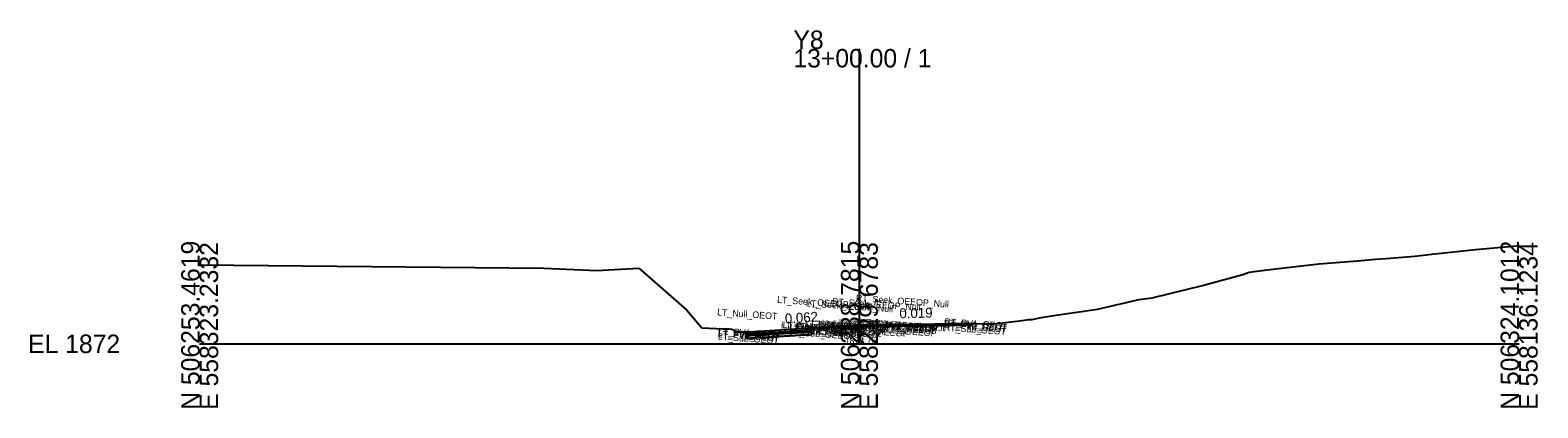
# Model space of a CAD drawing. Extents: x -26 to 203, y -10 to 8070.
# Drawn here: x -25.7 to 202.8, y 2990.3 to 3047.5 of the extents above; entities that cross this region are included whole.
import ezdxf

# ---------------------------------------------------------------- set-up
doc = ezdxf.new("R2010")
doc.units = 0
for name, color, linetype in [('Default', 7, 'Continuous'), ('Exist Cross Section Cell', 7, 'Continuous'), ('Exist XS Center Line Elevation Label', 7, 'Continuous'), ('Exist XS Ground Line', 7, 'Continuous'), ('Prop CMT Pvmt Course 1', 7, 'Continuous'), ('Prop CMT Pvmt Course 2', 7, 'Continuous'), ('Prop CMT Pvmt Course 3', 7, 'Continuous'), ('Prop CMT Pvmt Surface', 7, 'Continuous'), ('Prop CMT Subgrade Earthwork', 7, 'Continuous'), ('Prop XS Earthwork Shape', 7, 'Continuous'), ('Prop XS SE Text', 7, 'Continuous'), ('Typical Text Grade Point CELL', 7, 'Continuous')]:
    doc.layers.add(name, color=color, linetype=linetype)

msp = doc.modelspace()

# ---------------------------------------------------------------- linework, layer by layer
at = {"layer": 'Exist Cross Section Cell'}
for p, q in [((100, 3000), (100, 3044.65)), ((0, 3000), (100, 3000)), ((100, 3000), (200, 3000))]:
    msp.add_line(p, q, dxfattribs=at)
at = {"layer": 'Exist XS Ground Line'}
for p, q in [((193.38, 3014.3), (199.06, 3014.81)), ((199.06, 3014.81), (200, 3014.88)), ((161.8, 3011.18), (169.66, 3012.1)), ((169.66, 3012.1), (175.49, 3012.57)), ((175.49, 3012.57), (178.21, 3012.81)), ((178.21, 3012.81), (179.85, 3012.91)), ((179.85, 3012.91), (184.19, 3013.29)), ((184.19, 3013.29), (186.76, 3013.56)), ((186.76, 3013.56), (193.38, 3014.3)), ((0, 3011.97), (52.15, 3011.44)), ((52.15, 3011.44), (60.18, 3011.11)), ((60.18, 3011.11), (66.58, 3011.45)), ((66.58, 3011.45), (73.87, 3005.11)), ((152.37, 3008.94), (158.12, 3010.51)), ((158.12, 3010.51), (159.08, 3010.85)), ((159.08, 3010.85), (161.8, 3011.18)), ((144.4, 3006.97), (152.22, 3008.9)), ((152.22, 3008.9), (152.37, 3008.94)), ((129.13, 3004.24), (136.11, 3005.26)), ((136.11, 3005.26), (142.41, 3006.69)), ((142.41, 3006.69), (144.4, 3006.97)), ((73.87, 3005.11), (76.12, 3002.43)), ((100, 3002.75), (120.83, 3003.07)), ((120.83, 3003.07), (124.29, 3003.48)), ((124.29, 3003.48), (125.68, 3003.66)), ((125.68, 3003.66), (126.18, 3003.69)), ((126.18, 3003.69), (127.57, 3003.96)), ((127.57, 3003.96), (129.13, 3004.24)), ((76.12, 3002.43), (79.45, 3002.28)), ((79.45, 3002.28), (80.67, 3002.24)), ((80.67, 3002.24), (81.26, 3001.77)), ((81.26, 3001.77), (82.09, 3001.8)), ((82.09, 3001.8), (83.04, 3001.8)), ((83.04, 3001.8), (83.17, 3001.8)), ((83.17, 3001.8), (97.69, 3002.71)), ((97.69, 3002.71), (98.01, 3002.72)), ((98.01, 3002.72), (100, 3002.75))]:
    msp.add_line(p, q, dxfattribs=at)
at = {"layer": 'Prop CMT Pvmt Course 1'}
for points in [[(99.95, 3002.75), (101.95, 3002.8), (101.96, 3002.8), (105.93, 3002.89), (105.94, 3002.89), (117.1, 3003.08)], [(99.95, 3002.75), (97.95, 3002.71), (97.94, 3002.71), (93.96, 3002.45), (93.95, 3002.45), (82.79, 3001.69)], [(82.79, 3001.44), (92.79, 3002.06)], [(82.79, 3001.69), (82.79, 3001.44)]]:
    msp.add_lwpolyline(points, dxfattribs=at)
at = {"layer": 'Prop CMT Pvmt Course 2'}
for points in [[(92.79, 3002.06), (82.79, 3001.44)], [(82.79, 3001.19), (92.79, 3001.81)], [(82.79, 3001.44), (82.79, 3001.19)]]:
    msp.add_lwpolyline(points, dxfattribs=at)
at = {"layer": 'Prop CMT Pvmt Course 3'}
for points in [[(92.79, 3001.81), (82.79, 3001.19)], [(82.79, 3000.81), (92.79, 3001.43)], [(82.79, 3001.19), (82.79, 3000.81)]]:
    msp.add_lwpolyline(points, dxfattribs=at)
at = {"layer": 'Prop CMT Pvmt Surface'}
for points in [[(99.95, 3002.75), (101.95, 3002.8), (101.96, 3002.8), (105.93, 3002.89), (105.94, 3002.89), (117.1, 3003.08)], [(99.95, 3002.75), (97.95, 3002.71), (97.94, 3002.71), (93.96, 3002.45), (93.95, 3002.45), (82.79, 3001.69)]]:
    msp.add_lwpolyline(points, dxfattribs=at)
at = {"layer": 'Prop CMT Subgrade Earthwork'}
for points in [[(82.79, 3000.81), (82.79, 3001.76)], [(92.79, 3001.43), (82.79, 3000.81)], [(92.79, 3001.43), (92.79, 3002.41)]]:
    msp.add_lwpolyline(points, dxfattribs=at)
at = {"layer": 'Prop XS Earthwork Shape'}
msp.add_lwpolyline([(99.95, 3002.75), (97.95, 3002.71), (97.69, 3002.71), (93.96, 3002.45), (82.79, 3001.69), (82.79, 3000.81), (92.79, 3001.43), (92.79, 3002.25), (97.95, 3002.58), (117.1, 3002.83), (117.1, 3003.08)], close=True, dxfattribs=at)

# ---------------------------------------------------------------- texts
at = {"layer": 'Default'}
msp.add_text('-', height=0.0001, dxfattribs=at).set_placement((0, 3000))
at = {"layer": 'Exist Cross Section Cell'}
for s, p in [('Y8', (90, 3044.65)), ('13+00.00 / 1', (90, 3041.85)), ('EL 1872', (-26, 2998.6))]:
    msp.add_text(s, height=2.8, dxfattribs=at).set_placement(p)
for s, p in [('N 506253.4619', (0, 2990)), ('E 558323.2332', (2.8, 2990)), ('N 506288.7815', (100, 2990)), ('E 558229.6783', (102.8, 2990)), ('N 506324.1012', (200, 2990)), ('E 558136.1234', (202.8, 2990))]:
    msp.add_text(s, height=2.8, rotation=90, dxfattribs=at).set_placement(p)
at = {"layer": 'Exist XS Center Line Elevation Label'}
msp.add_text('1874.75', height=1, dxfattribs=at).set_placement((97.77, 3000))
at = {"layer": 'Prop XS SE Text'}
for s, rotation, p in [('0.019', 1.0866, (106.08, 3003.87)), ('0.062', 3.5571, (88.75, 3003.06))]:
    msp.add_text(s, height=1.5, rotation=rotation, dxfattribs=at).set_placement(p)
at = {"layer": 'Typical Text Grade Point CELL'}
for s, p in [('LT_Null_OEOT', (78.41, 3004.31)), ('LT_Seek_OEEOP_Null', (87.5, 3006.2)), ('LT_Seek_IEEOP_Null', (91.88, 3005.68)), ('RT_Seek_IEEOP_Null', (95.82, 3005.93)), ('RT_Seek_OEEOP_Null', (99.44, 3006.46)), ('LT_PV_Sub_Tie_Out', (88.09, 3002.36)), ('LT_Null OEEOP Test', (88.35, 3002.41)), ('LT_PV2_OEEOP', (89.32, 3001.95)), ('LT_PV1_OEEOP', (89.44, 3002.07)), ('LT_Pvmt Out', (90.2, 3002.21)), ('LT_Null IEEOP Test', (91.72, 3002.59)), ('LT_PV_Sub_Tie_In', (92.7, 3002.57)), ('LT_PV2_IEEOP', (93.7, 3002.18)), ('LT_PV1_IEEOP', (93.82, 3002.29)), ('Null RT Pvmt Slope', (94.21, 3002.65)), ('Null LT Pvmt Slope', (94.26, 3002.67)), ('PV1_Overlay_Null', (94.7, 3002.49)), ('LT_Pvmt In', (94.79, 3002.43)), ('RT_PV_Sub_Tie_In', (96.64, 3002.67)), ('RT_Null IEEOP Test', (96.66, 3002.72)), ('PV2_PGL', (97.27, 3002.19)), ('PV3_PGL', (97.27, 3001.94)), ('PV1_PGL', (97.39, 3002.43)), ('RT_PV2_IEEOP', (97.64, 3002.34)), ('RT_PV3_IEEOP', (97.64, 3002.09)), ('RT_PV1_IEEOP', (97.75, 3002.46)), ('RT_Pvmt In', (98.75, 3002.52)), ('CL', (99.14, 3002.06)), ('RT_Null OEEOP Test', (99.28, 3002.81)), ('RT_PV_Sub_Tie_Out', (100.03, 3002.8)), ('RT_PV2_OEEOP', (101.25, 3002.44)), ('RT_PV3_OEEOP', (101.25, 3002.19)), ('RT_PV1_OEEOP', (101.37, 3002.56)), ('RT_Pvmt Out', (102.12, 3002.66)), ('RT_PV2_OEOT', (112.76, 3002.63)), ('RT_PV3_OEOT', (112.76, 3002.38)), ('RT_Sub_OEOT', (112.78, 3002)), ('RT_PV1_OEOT', (112.88, 3002.87)), ('LT_PV2_OEOT', (78.51, 3001.24)), ('LT_PV3_OEOT', (78.51, 3000.99)), ('LT_Sub_OEOT', (78.54, 3000.61)), ('LT_PV1_OEOT', (78.63, 3001.48)), ('LT_PV3_OEEOP', (89.32, 3001.7)), ('LT_Sub_OEEOP', (89.34, 3001.33)), ('LT_PV3_IEEOP', (93.7, 3001.93)), ('LT_Sub_IEEOP', (93.72, 3001.55)), ('Sub_PGL', (97.29, 3001.56)), ('RT_Sub_IEEOP', (97.66, 3001.71)), ('RT_Sub_OEEOP', (101.28, 3001.82))]:
    msp.add_text(s, height=1, rotation=356, dxfattribs=at).set_placement(p)

doc.saveas('drawing.dxf')
